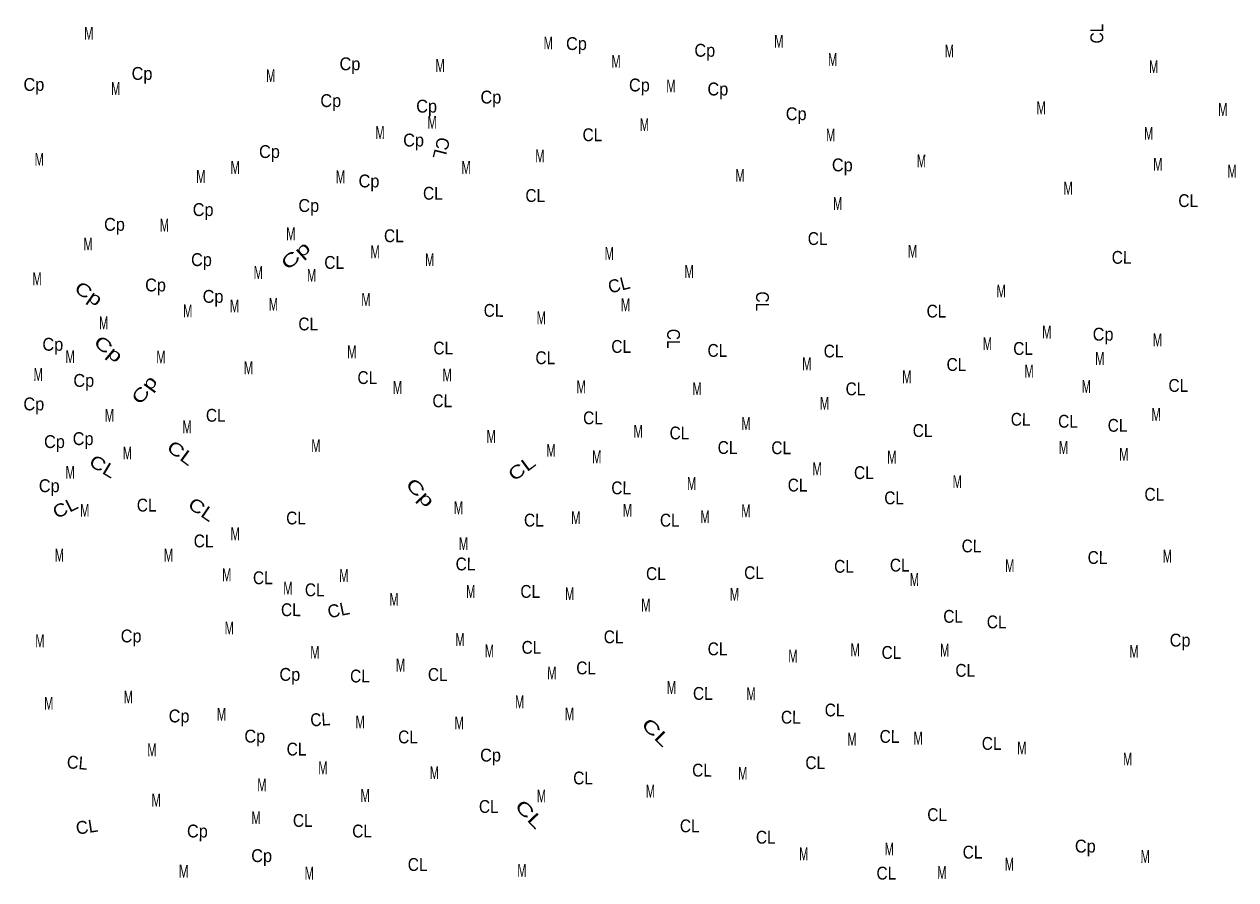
# Model space of a CAD drawing. Extents: x 713577 to 726626, y 7177731 to 7191794.
# Drawn here: x 713577 to 717165, y 7177927 to 7180459 of the extents above; entities that cross this region are included whole.
import ezdxf
from ezdxf.enums import TextEntityAlignment as Align

# ---------------------------------------------------------------- set-up
doc = ezdxf.new("R2010")
doc.units = 0
doc.header["$LTSCALE"] = 15
doc.layers.add('19', color=7, linetype='Continuous')

msp = doc.modelspace()

# ---------------------------------------------------------------- texts
at = {"layer": '19'}
for s, rotation, width, p in [('M', 359.905, 0.65, (713768.31, 7180412.57)), ('M', 359.905, 0.65, (715811.92, 7180389.1)), ('CL', 90, 0.9, (716772.65, 7180430.86)), ('M', 359.905, 0.65, (715129.04, 7180384.14)), ('Cp', 359.905, 0.95, (715212.55, 7180382.34)), ('Cp', 359.905, 0.95, (715592.65, 7180362.49)), ('M', 359.905, 0.65, (716316.95, 7180360.42)), ('Cp', 359.905, 0.95, (714541.67, 7180322.47)), ('M', 359.905, 0.65, (714808.78, 7180317.39)), ('M', 359.905, 0.65, (715329.78, 7180329.78)), ('M', 359.905, 0.65, (715971.24, 7180335.14)), ('Cp', 359.905, 0.95, (713925.86, 7180294)), ('M', 359.905, 0.65, (714306.98, 7180287.4)), ('M', 359.905, 0.65, (716922.06, 7180313.92)), ('Cp', 359.905, 0.95, (713605.66, 7180261.39)), ('M', 359.905, 0.65, (713847.91, 7180249.39)), ('Cp', 359.905, 0.95, (715398.93, 7180259.74)), ('M', 359.905, 0.65, (715492.39, 7180256.93)), ('Cp', 359.905, 0.95, (715631.4, 7180247.88)), ('Cp', 359.905, 0.95, (714484.82, 7180213.53)), ('Cp', 359.905, 0.95, (714959.09, 7180224.01)), ('Cp', 359.905, 0.95, (714768.81, 7180197.15)), ('Cp', 359.905, 0.95, (715863.27, 7180174.59)), ('M', 359.905, 0.65, (716588.76, 7180192.27)), ('M', 359.99, 0.65, (717126.89, 7180187.22)), ('M', 359.905, 0.65, (714784.97, 7180149.4)), ('M', 359.905, 0.65, (715413.82, 7180142.52)), ('M', 359.905, 0.65, (714630.82, 7180119.17)), ('M', 359.905, 0.65, (715965.24, 7180111.78)), ('M', 359.905, 0.65, (716907.21, 7180116.68)), ('Cp', 359.905, 0.95, (714730.2, 7180096.8)), ('M', 359.905, 0.65, (713621.54, 7180039.98)), ('Cp', 359.905, 0.95, (714303.29, 7180062.71)), ('M', 359.905, 0.65, (715104.46, 7180049.91)), ('M', 359.905, 0.65, (716234.22, 7180035.11)), ('M', 359.905, 0.65, (714201.8, 7180015.49)), ('M', 359.905, 0.65, (714885.67, 7180015.8)), ('Cp', 359.905, 0.95, (715999.89, 7180023.24)), ('M', 359.905, 0.65, (716934.44, 7180024.93)), ('M', 359.99, 0.65, (717154.17, 7180004.91)), ('M', 359.905, 0.65, (714100.01, 7179988.81)), ('M', 359.905, 0.65, (714513.61, 7179987.79)), ('Cp', 359.905, 0.95, (714598.1, 7179975.72)), ('M', 359.905, 0.65, (715696.93, 7179992.59)), ('CL', 359.905, 0.9, (714787.32, 7179939.34)), ('CL', 359.905, 0.9, (715090.55, 7179932.55)), ('M', 359.905, 0.65, (716668.77, 7179954.45)), ('Cp', 359.905, 0.95, (714106.81, 7179891.03)), ('Cp', 359.905, 0.95, (714419.68, 7179903.11)), ('M', 359.905, 0.65, (715986.11, 7179909.25)), ('CL', 359.905, 0.9, (717024.33, 7179917.57)), ('Cp', 359.905, 0.95, (713844.26, 7179847.39)), ('M', 359.905, 0.65, (713992.06, 7179845.16)), ('M', 359.905, 0.65, (714366.52, 7179819.35)), ('CL', 359.905, 0.9, (714671.78, 7179813.6)), ('M', 359.905, 0.65, (713765.95, 7179789.19)), ('CL', 359.905, 0.9, (715926.82, 7179805.22)), ('Cp', 359.905, 0.95, (714101.92, 7179742.9)), ('Cp', 41.835, 1.45, (714393.4, 7179760.31)), ('M', 359.905, 0.65, (714616.15, 7179766.04)), ('M', 359.905, 0.65, (714777.84, 7179742.9)), ('M', 359.905, 0.65, (715309.78, 7179761.24)), ('M', 359.905, 0.65, (716207.92, 7179767.7)), ('CL', 359.905, 0.9, (716827.12, 7179749.66)), ('CL', 359.905, 0.9, (714495.01, 7179734.69)), ('M', 359.905, 0.65, (715546.32, 7179707.82)), ('M', 359.905, 0.65, (713614.99, 7179686.37)), ('M', 359.905, 0.65, (714270.22, 7179704.84)), ('M', 359.905, 0.65, (714428.12, 7179696.42)), ('Cp', 325.558, 1.3, (713757.1, 7179645.64)), ('Cp', 359.905, 0.95, (713965.92, 7179667.89)), ('M', 359.905, 0.65, (716470.54, 7179649.95)), ('Cp', 359.905, 0.95, (714136.21, 7179634.14)), ('M', 359.905, 0.65, (714199.79, 7179605.53)), ('M', 359.905, 0.65, (714314.97, 7179610.77)), ('M', 359.905, 0.65, (714589.07, 7179624.9)), ('M', 359.905, 0.65, (715357.92, 7179609.37)), ('CL', 270, 0.9, (715744.45, 7179638.57)), ('M', 359.905, 0.65, (714061.24, 7179591.18)), ('CL', 359.905, 0.9, (714967.03, 7179592.72)), ('M', 359.905, 0.65, (715108.3, 7179570.68)), ('CL', 359.905, 0.9, (716278.76, 7179590.55)), ('M', 359.905, 0.65, (713812.29, 7179555.8)), ('CL', 359.905, 0.9, (714418.15, 7179552.54)), ('M', 359.905, 0.65, (716605.62, 7179528.56)), ('Cp', 359.905, 0.95, (713661.72, 7179492.42)), ('Cp', 320.095, 1.4, (713814.5, 7179483.08)), ('CL', 270, 0.9, (715481.13, 7179527.98)), ('M', 359.905, 0.65, (716429.58, 7179494.38)), ('Cp', 359.99, 0.95, (716772.29, 7179522.28)), ('M', 359.905, 0.65, (716933.25, 7179505.38)), ('M', 359.905, 0.65, (713713.03, 7179455.88)), ('M', 359.905, 0.65, (714547.38, 7179469.87)), ('CL', 359.905, 0.9, (714818.04, 7179481.28)), ('CL', 359.905, 0.9, (715345, 7179486.04)), ('CL', 359.905, 0.9, (715629.99, 7179474.3)), ('CL', 359.905, 0.9, (715974, 7179472.41)), ('CL', 359.905, 0.9, (716535.35, 7179480.03)), ('M', 359.905, 0.65, (713981.81, 7179454.77)), ('M', 359.905, 0.65, (714241.08, 7179422.98)), ('CL', 359.905, 0.9, (715120.25, 7179452.61)), ('M', 359.905, 0.65, (715894.85, 7179434.82)), ('CL', 359.905, 0.9, (716338.02, 7179432.56)), ('M', 359.905, 0.65, (716762.61, 7179450.24)), ('M', 359.905, 0.65, (713618.49, 7179403.01)), ('Cp', 359.905, 0.95, (713753.35, 7179385.55)), ('CL', 359.905, 0.9, (714593.2, 7179393.83)), ('M', 359.905, 0.65, (714829.63, 7179401.46)), ('M', 359.905, 0.65, (716191.13, 7179396.02)), ('M', 359.905, 0.65, (716553.06, 7179412.98)), ('Cp', 53.942, 1.35, (713948.12, 7179365.5)), ('M', 359.905, 0.65, (714682.43, 7179364.58)), ('M', 359.905, 0.65, (715226.28, 7179366.33)), ('M', 359.905, 0.65, (715569.61, 7179361.13)), ('M', 359.905, 0.65, (716722.56, 7179367.77)), ('CL', 359.905, 0.9, (716995.05, 7179370.62)), ('Cp', 359.905, 0.95, (713605.42, 7179315.87)), ('CL', 359.905, 0.9, (714815.13, 7179325.19)), ('M', 359.905, 0.65, (715947.08, 7179317.88)), ('M', 359.905, 0.65, (713829.4, 7179282.03)), ('CL', 359.905, 0.9, (714144.29, 7179282.23)), ('M', 359.905, 0.65, (716929.26, 7179284.63)), ('M', 359.905, 0.65, (714059.18, 7179247.97)), ('CL', 359.905, 0.9, (715261.46, 7179274.74)), ('M', 359.905, 0.65, (715714.6, 7179258.15)), ('CL', 359.905, 0.9, (716527.98, 7179270.52)), ('CL', 359.905, 0.9, (716668.3, 7179264.61)), ('CL', 359.905, 0.9, (716815.08, 7179252.49)), ('Cp', 359.905, 0.95, (713666.55, 7179204.41)), ('Cp', 359.905, 0.95, (713751.41, 7179213.22)), ('M', 359.905, 0.65, (714959.91, 7179219.63)), ('M', 359.905, 0.65, (715395.41, 7179234.81)), ('CL', 359.905, 0.9, (715517.57, 7179229.91)), ('CL', 359.905, 0.9, (716237.61, 7179237.2)), ('M', 359.905, 0.65, (713882.41, 7179170.71)), ('CL', 323.771, 1.3, (714030.1, 7179174.47)), ('M', 359.905, 0.65, (714440.87, 7179192.32)), ('M', 359.905, 0.65, (715137.15, 7179178.57)), ('CL', 359.905, 0.9, (715660.01, 7179186.92)), ('CL', 359.905, 0.9, (715818.95, 7179186.19)), ('M', 359.905, 0.65, (716654.97, 7179187.11)), ('CL', 329.051, 1.25, (713800.37, 7179133.82)), ('M', 359.905, 0.65, (715272.66, 7179159.13)), ('M', 359.905, 0.65, (716146.66, 7179158.47)), ('M', 359.905, 0.65, (716833.73, 7179166.69)), ('M', 359.905, 0.65, (713713.13, 7179113.53)), ('CL', 36.573, 1.3, (715061.8, 7179129.5)), ('M', 359.905, 0.65, (715925.22, 7179124.04)), ('CL', 359.905, 0.9, (716063.74, 7179112.54)), ('Cp', 359.905, 0.95, (713651.09, 7179073.86)), ('Cp', 313.06, 1.45, (714736.18, 7179059.61)), ('CL', 359.905, 0.9, (715344.97, 7179067.47)), ('M', 359.905, 0.65, (715553.57, 7179080.45)), ('CL', 359.905, 0.9, (715867.48, 7179075.75)), ('M', 359.905, 0.65, (716340.42, 7179085.9)), ('CL', 359.905, 0.9, (716153.43, 7179037.83)), ('CL', 359.905, 0.9, (716923.93, 7179048.45)), ('CL', 26.486, 1.15, (713706.74, 7179010.81)), ('M', 359.905, 0.65, (713756.19, 7179000.9)), ('CL', 359.905, 0.9, (713939.69, 7179016.44)), ('CL', 325.929, 1.25, (714092.14, 7179006.95)), ('M', 359.905, 0.65, (714863.12, 7179008.68)), ('M', 359.905, 0.65, (715363.54, 7179001.22)), ('M', 359.905, 0.65, (715714.57, 7178999.45)), ('CL', 359.905, 0.9, (714382.07, 7178978.26)), ('CL', 359.905, 0.9, (715086.31, 7178972.12)), ('M', 359.905, 0.65, (715210.72, 7178979.27)), ('CL', 359.905, 0.9, (715488.97, 7178971.78)), ('M', 359.905, 0.65, (715593.18, 7178982.28)), ('M', 359.905, 0.65, (714201.82, 7178931.56)), ('CL', 359.905, 0.9, (714108.21, 7178910.44)), ('M', 359.905, 0.65, (714877.86, 7178902.6)), ('CL', 359.905, 0.9, (716382.53, 7178895.6)), ('M', 359.905, 0.65, (713681.07, 7178868.46)), ('M', 359.905, 0.65, (714004.33, 7178868.26)), ('CL', 359.905, 0.9, (716755.71, 7178861.36)), ('M', 359.905, 0.65, (716962.54, 7178865.63)), ('M', 359.905, 0.65, (714176.77, 7178810.31)), ('CL', 359.905, 0.9, (714883.93, 7178842.21)), ('CL', 359.905, 0.9, (715447.81, 7178813.63)), ('CL', 359.905, 0.9, (715738.47, 7178816.47)), ('CL', 359.905, 0.9, (716004.95, 7178835.25)), ('CL', 359.905, 0.9, (716170, 7178838.95)), ('M', 359.905, 0.65, (716495.77, 7178837.08)), ('CL', 359.905, 0.9, (714283.68, 7178801.45)), ('M', 359.905, 0.65, (714523.75, 7178808.08)), ('M', 359.905, 0.65, (716213.34, 7178796.13)), ('M', 359.905, 0.65, (714357.98, 7178770.57)), ('CL', 359.905, 0.9, (714437.39, 7178765.73)), ('M', 359.905, 0.65, (714899.3, 7178760.72)), ('CL', 359.905, 0.9, (715075.68, 7178761.03)), ('M', 359.905, 0.65, (715192.45, 7178754.27)), ('M', 359.905, 0.65, (715680.42, 7178752.34)), ('CL', 359.905, 0.9, (714366.7, 7178706.86)), ('M', 359.905, 0.65, (714672.24, 7178737.57)), ('M', 359.905, 0.65, (715418.15, 7178720.56)), ('CL', 359.905, 0.9, (716328.17, 7178687.23)), ('CL', 359.905, 0.9, (716457.06, 7178670.78)), ('M', 359.905, 0.65, (714184.26, 7178652.87)), ('M', 359.905, 0.65, (713623.45, 7178615.03)), ('Cp', 359.905, 0.95, (713893.51, 7178629.3)), ('M', 359.905, 0.65, (714867.58, 7178618.93)), ('CL', 359.905, 0.9, (715079.32, 7178595.51)), ('CL', 359.905, 0.9, (715322.56, 7178626.59)), ('Cp', 359.99, 0.95, (717000.27, 7178616.85)), ('M', 359.905, 0.65, (714438, 7178580.87)), ('M', 359.905, 0.65, (714954.68, 7178584.98)), ('CL', 359.905, 0.9, (715630.38, 7178590.95)), ('M', 359.905, 0.65, (715853.71, 7178569.71)), ('M', 359.905, 0.65, (716038.01, 7178587.96)), ('CL', 359.905, 0.9, (716145.38, 7178580.49)), ('M', 359.905, 0.65, (716303.13, 7178587.19)), ('M', 359.905, 0.65, (716863.77, 7178583.75)), ('M', 359.905, 0.65, (714691.47, 7178543)), ('CL', 359.905, 0.9, (715241.21, 7178534.6)), ('CL', 359.905, 0.9, (716364.03, 7178527.43)), ('Cp', 359.905, 0.95, (714363.59, 7178515.5)), ('CL', 359.905, 0.9, (714571.32, 7178510.59)), ('CL', 359.905, 0.9, (714801.79, 7178515.11)), ('M', 359.905, 0.65, (715139.77, 7178519.85)), ('M', 359.905, 0.65, (715493.97, 7178476.51)), ('CL', 359.905, 0.9, (715586.82, 7178459.19)), ('M', 359.905, 0.65, (715729.58, 7178458.23)), ('M', 359.905, 0.65, (713649.65, 7178430.06)), ('M', 359.905, 0.65, (713885.32, 7178448.56)), ('M', 359.905, 0.65, (715044.18, 7178434.51)), ('Cp', 359.905, 0.95, (714035.62, 7178392.43)), ('M', 359.905, 0.65, (714161.3, 7178397.39)), ('CL', 4.036, 0.9, (714454.87, 7178382.28)), ('M', 359.905, 0.65, (715191.93, 7178398.14)), ('CL', 359.905, 0.9, (715847.46, 7178388.76)), ('CL', 359.905, 0.9, (715977.07, 7178410.09)), ('M', 359.905, 0.65, (714571.88, 7178374.51)), ('M', 359.905, 0.65, (714865.18, 7178371.7)), ('CL', 315, 1.45, (715435.45, 7178349.43)), ('Cp', 359.905, 0.95, (714259.89, 7178332.74)), ('CL', 359.905, 0.9, (714713.6, 7178330.33)), ('M', 359.905, 0.65, (716028.62, 7178323.84)), ('CL', 359.905, 0.9, (716139.67, 7178331.94)), ('M', 359.905, 0.65, (716224.49, 7178326.83)), ('CL', 359.905, 0.9, (716442.21, 7178311.22)), ('M', 0.199, 0.65, (713955.39, 7178292.06)), ('CL', 359.905, 0.9, (714383.45, 7178294.42)), ('M', 359.905, 0.65, (716531.66, 7178297.49)), ('CL', 355.096, 0.95, (713732.66, 7178254.51)), ('M', 359.905, 0.65, (714461.63, 7178239.14)), ('CL', 359.905, 0.9, (715919.81, 7178254.09)), ('M', 359.905, 0.65, (716844.77, 7178265.12)), ('M', 359.905, 0.65, (714791.63, 7178224.81)), ('CL', 359.905, 0.9, (715232.12, 7178208.9)), ('CL', 359.905, 0.9, (715584.39, 7178232.11)), ('M', 359.905, 0.65, (715704.99, 7178222.63)), ('M', 359.905, 0.65, (714280.93, 7178188.41)), ('M', 359.905, 0.65, (715431.49, 7178170.06)), ('M', 0.199, 0.65, (713967.97, 7178143.45)), ('M', 359.905, 0.65, (714586.7, 7178157.21)), ('M', 359.905, 0.65, (715108.67, 7178155.68)), ('CL', 359.905, 0.9, (714952.93, 7178124.52)), ('CL', 313.32, 1.45, (715059.75, 7178107.66)), ('CL', 359.905, 0.9, (716280.8, 7178100.38)), ('M', 359.905, 0.65, (714263.53, 7178091.33)), ('CL', 359.905, 0.9, (714401.93, 7178083.35)), ('CL', 359.905, 0.9, (715548.05, 7178067.19)), ('Cp', 359.905, 0.95, (714089.86, 7178051.91)), ('CL', 359.905, 0.9, (714577.65, 7178051.9)), ('CL', 359.905, 0.9, (715773.29, 7178033.61)), ('M', 359.905, 0.65, (715885.55, 7177984.38)), ('M', 359.905, 0.65, (716139.1, 7177998.87)), ('CL', 359.905, 0.9, (716385.67, 7177989.52)), ('Cp', 359.905, 0.95, (716719.65, 7178007.37)), ('Cp', 359.905, 0.95, (714280.18, 7177979.09)), ('CL', 359.905, 0.9, (714742.2, 7177952.87)), ('M', 359.905, 0.65, (716494.63, 7177953.87)), ('M', 359.905, 0.65, (716897.07, 7177976.39)), ('M', 358.704, 0.7, (714048.87, 7177933.04)), ('M', 359.905, 0.65, (714421.28, 7177927.15)), ('M', 359.905, 0.65, (715050.97, 7177935.39)), ('CL', 359.905, 0.9, (716130.38, 7177927.3)), ('M', 359.905, 0.65, (716295.08, 7177929.35))]:
    msp.add_text(s, height=38, rotation=rotation, dxfattribs=dict(at, width=width)).set_placement(p, align=Align.CENTER)
for s, width, p in [('CL', 0.9, (715259.86, 7180112.55)), ('CL', 0.9, (716038.96, 7179360.48)), ('Cp', 0.95, (714958.15, 7178276.63))]:
    msp.add_text(s, height=38, dxfattribs=dict(at, width=width)).set_placement(p, align=Align.CENTER)
for rotation, p in [(256.065, (714794.15, 7180095.84)), (14.276, (715343.06, 7179669.46)), (11.585, (714511.53, 7178706.81)), (8.456, (713765.08, 7178064.89))]:
    msp.add_text('CL', height=38, rotation=rotation, dxfattribs=at).set_placement(p, align=Align.CENTER)

doc.saveas('drawing.dxf')
